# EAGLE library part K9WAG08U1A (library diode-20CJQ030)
Samsung's K9WAG08U1A 1G x 8 Bit / 2G x 8 Bit / 4G x 8 Bit NAND Flash Memory Description: Offered in 1G x 8bit, the K9K8G08U0A is a 8G-bit NAND Flash Memory with spare 256M-bit. Its NAND cell provides the most costeffective solution for the solid state application market. A program operation can be performed in typical 200µs on the (2K+64)Byte page and an erase operation can be performed in typical 1.5ms on a (128K+4K)Byte block. Data in the data register can be read out at 25ns(K9NBG08U5A : 50ns) cycle time per Byte. The I/O pins serve as the ports for address and data input/output as well as command input. The on-chip write controller automates all program and erase functions including pulse repetition, where required, and internal verification and margining of data. Even the write-intensive systems can take advantage of the K9K8G08U0A?s extended reliability of 100K program/erase cycles by providing ECC(Error Correcting Code) with real time mapping-out algorithm. The K9K8G08U0A is an optimum solution for large nonvolatile storage applications such as solid state file storage and other portable applications requiring non-volatility. An ultra high density solution having two 8Gb stacked with two chip selects is also available in standard TSOPI package and another ultra high density solution having two 16Gb TSOPI package stacked with four chip selects is also available in TSOPI-DSP. Features: Voltage Supply - 2.70V ~ 3.60V Organization - Memory Cell Array : (1G + 32M) - Data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
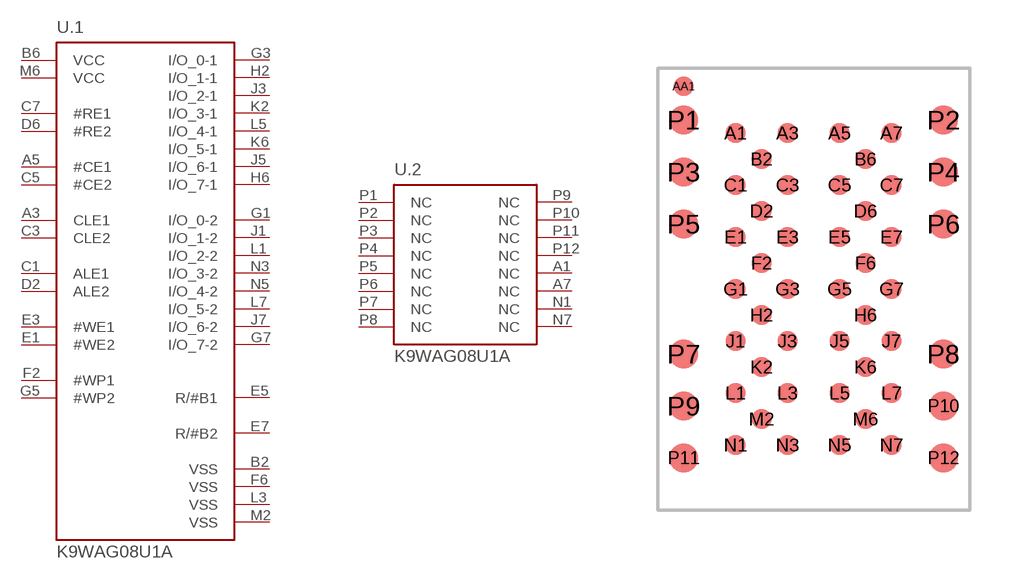
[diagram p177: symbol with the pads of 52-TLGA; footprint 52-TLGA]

Designator prefix U; gates .1=K9WAG08U1A .2=K9WAG08U1A_NC

## K9WAG08U1A-I  [52-TLGA]
A1  .2:NC  nc
A3  .1:CLE1  in
A5  .1:#CE1  in
A7  .2:NC  nc
B2  .1:VSS  pwr
B6  .1:VCC  in
C1  .1:ALE1  in
C3  .1:CLE2  in
C5  .1:#CE2  in
C7  .1:#RE1  in
D2  .1:ALE2  in
D6  .1:#RE2  in
E1  .1:#WE2  in
E3  .1:#WE1  in
E5  .1:R/#B1  in
E7  .1:R/#B2  in
F2  .1:#WP1  in
F6  .1:VSS  pwr
G1  .1:I/O_0-2
G3  .1:I/O_0-1
G5  .1:#WP2  in
G7  .1:I/O_7-2
H2  .1:I/O_1-1
H6  .1:I/O_7-1
J1  .1:I/O_1-2
J3  .1:I/O_2-1
J5  .1:I/O_6-1
J7  .1:I/O_6-2
K2  .1:I/O_3-1
K6  .1:I/O_5-1
L1  .1:I/O_2-2
L3  .1:VSS  pwr
L5  .1:I/O_4-1
L7  .1:I/O_5-2
M2  .1:VSS  pwr
M6  .1:VCC  in
N1  .2:NC  nc
N3  .1:I/O_3-2
N5  .1:I/O_4-2
N7  .2:NC  nc
P1  .2:NC  nc
P2  .2:NC  nc
P3  .2:NC  nc
P4  .2:NC  nc
P5  .2:NC  nc
P6  .2:NC  nc
P7  .2:NC  nc
P8  .2:NC  nc
P9  .2:NC  nc
P10  .2:NC  nc
P11  .2:NC  nc
P12  .2:NC  nc

## Footprint 52-TLGA (pad centres in mm)
Smasung's FLASH MEMORY K9WAG08U1A K9K8G08U0A K9NBG08U5A
smd 0.75 x 0.75: A1 -3,6; A3 -1,6; A5 1,6; A7 3,6; AA1 -5,7.8; B2 -2,5; B6 2,5; C1 -3,4; C3 -1,4; C5 1,4; C7 3,4; D2 -2,3; D6 2,3; E1 -3,2; E3 -1,2; E5 1,2; E7 3,2; F2 -2,1; F6 2,1; G1 -3,0; G3 -1,0; G5 1,0; G7 3,0; H2 -2,-1; H6 2,-1; J1 -3,-2; J3 -1,-2; J5 1,-2; J7 3,-2; K2 -2,-3; K6 2,-3; L1 -3,-4; L3 -1,-4; L5 1,-4; L7 3,-4; M2 -2,-5; M6 2,-5; N1 -3,-6; N3 -1,-6; N5 1,-6; N7 3,-6
smd 1.1 x 1.1: P1 -5,6.5; P2 5,6.5; P3 -5,4.5; P4 5,4.5; P5 -5,2.5; P6 5,2.5; P7 -5,-2.5; P8 5,-2.5; P9 -5,-4.5; P10 5,-4.5; P11 -5,-6.5; P12 5,-6.5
